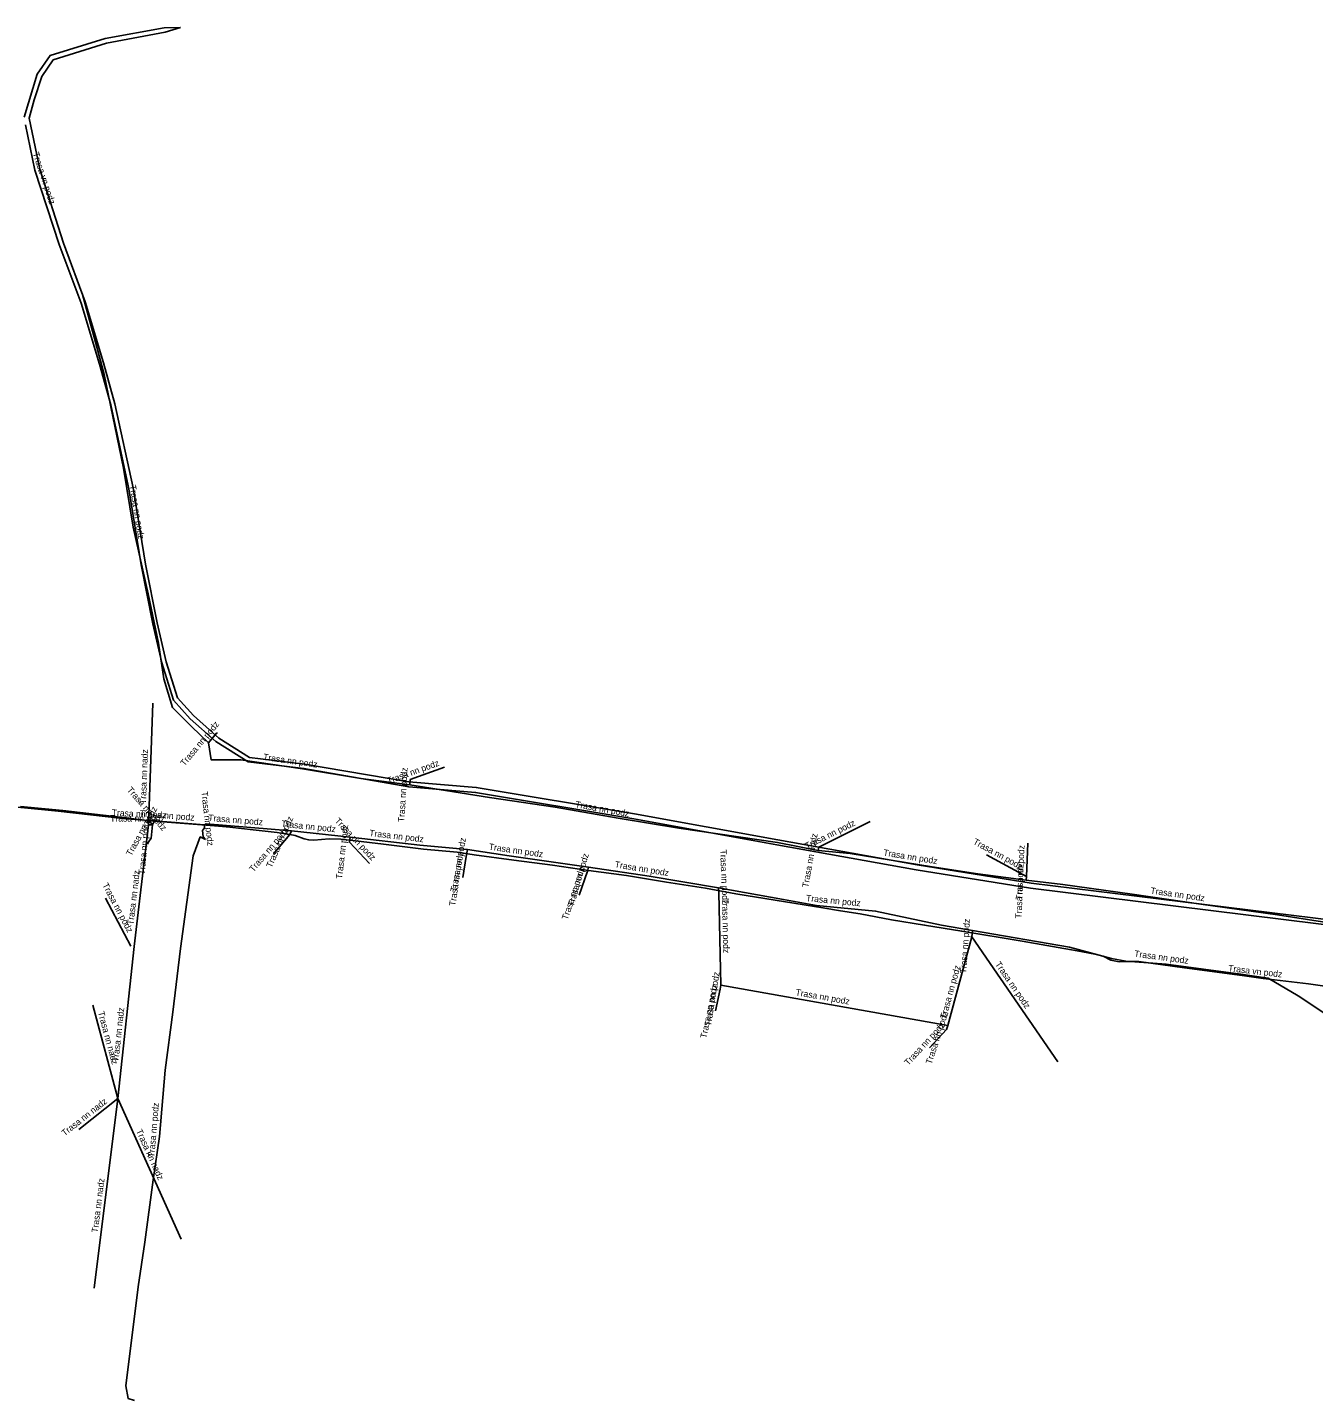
# Model space of a CAD drawing. Extents: x -704145 to -701313, y -1010090 to -1008177.
# Drawn here: x -702526.6 to -702325.8, y -1008863.1 to -1008648.8 of the extents above; entities that cross this region are included whole.
import ezdxf

# ---------------------------------------------------------------- set-up
doc = ezdxf.new("R2010")
doc.units = 0
for name, color, linetype in [('Level 11', 7, 'Continuous'), ('Level 20', 7, 'Continuous'), ('Level 21', 7, 'Continuous')]:
    doc.layers.add(name, color=color, linetype=linetype)

msp = doc.modelspace()

# ---------------------------------------------------------------- linework, layer by layer
at = {"layer": 'Level 11'}
for p, q in [((-702507.7, -1008773.21), (-702507.03, -1008754.23)), ((-702466.87, -1008766.17), (-702461.51, -1008764.24)), ((-702466.92, -1008767), (-702466.87, -1008766.17)), ((-702509.95, -1008792.21), (-702507.7, -1008773.21)), ((-702507.7, -1008773.21), (-702507.1, -1008773.21)), ((-702507.1, -1008773.21), (-702507.66, -1008772.57)), ((-702507.66, -1008772.57), (-702506.77, -1008772.61)), ((-702507.1, -1008773.21), (-702506.77, -1008772.61)), ((-702506.77, -1008772.61), (-702498.94, -1008773.22)), ((-702403.08, -1008776.71), (-702395.05, -1008772.73)), ((-702485.62, -1008774.72), (-702488.13, -1008777.68)), ((-702485.39, -1008774.19), (-702485.62, -1008774.72)), ((-702485.39, -1008774.19), (-702476.23, -1008775.13)), ((-702476.23, -1008775.13), (-702476.32, -1008775.93)), ((-702476.32, -1008775.93), (-702473.18, -1008779.25)), ((-702457.93, -1008777.1), (-702458.12, -1008778.18)), ((-702403.17, -1008777.23), (-702403.08, -1008776.71)), ((-702370.66, -1008781.3), (-702370.43, -1008776.08)), ((-702458.12, -1008778.18), (-702458.62, -1008781.44)), ((-702439.01, -1008779.84), (-702439.19, -1008780.46)), ((-702370.66, -1008781.3), (-702376.9, -1008777.9)), ((-702439.19, -1008780.46), (-702440.45, -1008784.23)), ((-702370.68, -1008781.88), (-702370.66, -1008781.3)), ((-702418.72, -1008783.05), (-702418.69, -1008783.77)), ((-702418.36, -1008798.26), (-702418.69, -1008783.77)), ((-702510.45, -1008792.15), (-702514.43, -1008784.66)), ((-702379.08, -1008789.71), (-702379.15, -1008790.71)), ((-702512.5, -1008815.97), (-702509.95, -1008792.21)), ((-702382.94, -1008804.53), (-702379.15, -1008790.71)), ((-702379.15, -1008790.71), (-702365.75, -1008810.2)), ((-702418.46, -1008798.9), (-702419.18, -1008802.25)), ((-702418.46, -1008798.89), (-702418.36, -1008798.26)), ((-702418.36, -1008798.26), (-702382.94, -1008804.53)), ((-702512.5, -1008815.97), (-702516.42, -1008801.39)), ((-702383.14, -1008805.17), (-702385.77, -1008808.02)), ((-702383.14, -1008805.17), (-702382.94, -1008804.53)), ((-702518.59, -1008820.78), (-702512.5, -1008815.97)), ((-702516.2, -1008845.55), (-702512.5, -1008815.97)), ((-702512.5, -1008815.97), (-702502.61, -1008837.9))]:
    msp.add_line(p, q, dxfattribs=at)
for points in [[(-702498.36, -1008760.45), (-702500.98, -1008757.87), (-702503.96, -1008754.9), (-702505.32, -1008750.45), (-702506.13, -1008744.89), (-702507.78, -1008737.15), (-702510.11, -1008726.77), (-702511.61, -1008717.57), (-702514.63, -1008702.91), (-702515.98, -1008697.86), (-702517.99, -1008690.46)], [(-702498.36, -1008760.45), (-702497.09, -1008758.92), (-702496.92, -1008758.89)], [(-702466.92, -1008767), (-702474.58, -1008766), (-702483.68, -1008764.49), (-702493.31, -1008763.1), (-702497.94, -1008763.07), (-702498.36, -1008760.45)], [(-702574.63, -1008766.64), (-702571.83, -1008766.98), (-702567.31, -1008767.31), (-702562.98, -1008767.5), (-702558.84, -1008768.14), (-702555.09, -1008768.64), (-702550.77, -1008768.98), (-702546.03, -1008769.22), (-702540.72, -1008769.59), (-702532.11, -1008770.1), (-702527.04, -1008770.58), (-702521.81, -1008771.09), (-702511.74, -1008772.25), (-702507.66, -1008772.57)], [(-702403.17, -1008777.23), (-702409.53, -1008776), (-702424.9, -1008773.73), (-702434.36, -1008772.2), (-702444.24, -1008770.45), (-702454.45, -1008768.95), (-702466.92, -1008767)], [(-702507.85, -1008776.25), (-702507.68, -1008775.84), (-702507.29, -1008775.3), (-702507.1, -1008773.21)], [(-702498.94, -1008773.22), (-702498.95, -1008773.7), (-702499.27, -1008774.13), (-702499.16, -1008775.09), (-702498.81, -1008775.5)], [(-702485.39, -1008774.19), (-702498.69, -1008773.08), (-702498.94, -1008773.22)], [(-702509.91, -1008863.1), (-702510.87, -1008862.8), (-702511.26, -1008860.79), (-702509.32, -1008845.37), (-702508.26, -1008838.38), (-702506.97, -1008828.63), (-702506.01, -1008821.86), (-702505.12, -1008811.51), (-702503.91, -1008802.49), (-702502.7, -1008792.55), (-702500.72, -1008778.07), (-702499.64, -1008775.12), (-702498.81, -1008775.5)], [(-702476.23, -1008775.13), (-702465.34, -1008776.41), (-702457.93, -1008777.1)], [(-702457.93, -1008777.1), (-702451.39, -1008778.07), (-702439.01, -1008779.84)], [(-702370.68, -1008781.88), (-702378.25, -1008780.9), (-702385.38, -1008779.76), (-702398.16, -1008777.7), (-702403.17, -1008777.23)], [(-702439.01, -1008779.84), (-702429.55, -1008781.26), (-702418.72, -1008783.05)], [(-702319.73, -1008789.11), (-702331.45, -1008787.28), (-702343.42, -1008785.6), (-702354.15, -1008784.06), (-702364.94, -1008782.53), (-702370.68, -1008781.88)], [(-702418.72, -1008783.05), (-702408.57, -1008784.89), (-702403.41, -1008785.8), (-702394.19, -1008786.68), (-702383.89, -1008788.91), (-702379.08, -1008789.71)], [(-702379.08, -1008789.71), (-702363.94, -1008792.3), (-702357.38, -1008794.12), (-702355.12, -1008794.5), (-702348.84, -1008794.98), (-702337.2, -1008796.54), (-702332.91, -1008797.14), (-702328.21, -1008799.91), (-702321.26, -1008804.56), (-702318.47, -1008806.08)]]:
    msp.add_lwpolyline(points, dxfattribs=at)
at = {"layer": 'Level 21'}
for points in [[(-702502.7, -1008648.75), (-702505.25, -1008648.79), (-702514.45, -1008650.49), (-702523.08, -1008653.11), (-702525.1, -1008656.06), (-702527.13, -1008662.73)], [(-702309.05, -1008789.82), (-702369.89, -1008782.31), (-702387.71, -1008779.45), (-702409.46, -1008775.55), (-702431.83, -1008771.52), (-702456.54, -1008767.39), (-702467.04, -1008766.5), (-702483.34, -1008763.74), (-702491.93, -1008762.71), (-702496.75, -1008759.68), (-702500.69, -1008756.17), (-702503.19, -1008753.41), (-702504.95, -1008747.76), (-702506.36, -1008741.71), (-702508.16, -1008732.51), (-702510.1, -1008720.64), (-702512.94, -1008707.51), (-702514.71, -1008701.13), (-702517.58, -1008691.56), (-702520.98, -1008682.4), (-702524.68, -1008670.85), (-702526.34, -1008662.93), (-702525.56, -1008660.05), (-702524.37, -1008656.42), (-702522.59, -1008653.82), (-702514.28, -1008651.18), (-702505.12, -1008649.48), (-702502.7, -1008648.75)], [(-702526.91, -1008663.97), (-702525.46, -1008671.05), (-702521.64, -1008682.63), (-702518.24, -1008691.78), (-702515.38, -1008701.32), (-702513.61, -1008707.68), (-702510.79, -1008720.77), (-702508.85, -1008732.64), (-702507.04, -1008741.86), (-702505.62, -1008747.94), (-702503.82, -1008753.76), (-702501.18, -1008756.67), (-702497.17, -1008760.24), (-702492.16, -1008763.39), (-702483.44, -1008764.43), (-702467.08, -1008767.3), (-702456.64, -1008768.18), (-702431.96, -1008772.31), (-702409.6, -1008776.34), (-702387.84, -1008780.24), (-702370.01, -1008783.1), (-702313.69, -1008790.08)], [(-702527.68, -1008770.39), (-702521.06, -1008770.97), (-702512.09, -1008772.04), (-702507.5, -1008772.62), (-702506.8, -1008772.65), (-702498.69, -1008773.28), (-702496.16, -1008773.5), (-702496.13, -1008773.5)], [(-702496.13, -1008773.5), (-702495.03, -1008773.6), (-702491.35, -1008774), (-702487.64, -1008774.44), (-702485.62, -1008774.72), (-702484.83, -1008774.9), (-702483.41, -1008775.42), (-702482.7, -1008775.59), (-702481.91, -1008775.62), (-702479.52, -1008775.41), (-702477.7, -1008775.49), (-702477.39, -1008775.52), (-702476.2, -1008775.62), (-702475.37, -1008775.72), (-702473.21, -1008775.98), (-702471.01, -1008776.26), (-702464.75, -1008777.02), (-702459.53, -1008777.49), (-702456.88, -1008777.89), (-702450.65, -1008778.73), (-702444.62, -1008779.5), (-702439.01, -1008780.36), (-702433.11, -1008781.16), (-702426.82, -1008782.18), (-702420.75, -1008783.12), (-702416.02, -1008783.98), (-702409.86, -1008784.99), (-702402.41, -1008786.16), (-702399.65, -1008786.65), (-702396.63, -1008787.12), (-702391.7, -1008788.07), (-702386.54, -1008788.88), (-702380.75, -1008789.85), (-702371.34, -1008791.41), (-702362.75, -1008792.91), (-702359.96, -1008793.4), (-702358.65, -1008793.75), (-702357.48, -1008794.34), (-702356.17, -1008794.62), (-702354.92, -1008794.54), (-702353.09, -1008794.55), (-702345.99, -1008795.55), (-702336.95, -1008796.76), (-702333.67, -1008797.23), (-702326.62, -1008798.05), (-702321.84, -1008798.75)]]:
    msp.add_lwpolyline(points, dxfattribs=at)

# ---------------------------------------------------------------- texts
at = {"layer": 'Level 20'}
for s, rotation, p in [('Trasa vn podz', 288.2462, (-702525.8, -1008668.4)), ('Trasa nn podz', 279.2602, (-702510.67, -1008720.25)), ('Trasa nn podz', 50.3051, (-702502.07, -1008764.14)), ('Trasa nn nadz', 87.9658, (-702508.09, -1008769.99)), ('Trasa nn podz', 351.7866, (-702489.86, -1008763.09)), ('Trasa nn podz', 19.8345, (-702470.27, -1008766.87)), ('Trasa nn podz', 86.5526, (-702467.77, -1008772.83)), ('Trasa nn podz', 311.1859, (-702511.14, -1008767.83)), ('Trasa nn podz', 276.5366, (-702499.46, -1008768.07)), ('Trasa nn podz', 357.4266, (-702513.47, -1008771.81)), ('Trasa nn podz', 61.1892, (-702510.4, -1008778.18)), ('Trasa nn podz', 355.5453, (-702509.08, -1008771.93)), ('Trasa nn podz', 349.9556, (-702441.14, -1008770.49)), ('Trasa nn podz', 84.8056, (-702508.31, -1008781.03)), ('Trasa nn podz', 355.2292, (-702498.41, -1008772.6)), ('Trasa nn podz', 66.541, (-702488.47, -1008780.02)), ('Trasa nn podz', 354.1408, (-702487.01, -1008773.52)), ('Trasa nn podz', 313.4044, (-702478.71, -1008772.68)), ('Trasa nn podz', 83.5812, (-702477.47, -1008781.72)), ('Trasa nn podz', 26.3363, (-702404.92, -1008777.06)), ('Trasa nn podz', 49.7186, (-702491.32, -1008780.68)), ('Trasa nn podz', 353.2963, (-702473.28, -1008774.97)), ('Trasa nn podz', 80.0223, (-702459.61, -1008783.74)), ('Trasa nn podz', 80.1807, (-702404.69, -1008783.08)), ('Trasa nn podz', 331.4449, (-702379.07, -1008776.16)), ('Trasa nn podz', 81.3568, (-702459.81, -1008785.95)), ('Trasa nn podz', 351.8634, (-702454.63, -1008777.1)), ('Trasa nn podz', 73.8108, (-702441.33, -1008786.05)), ('Trasa nn podz', 272.3859, (-702418.47, -1008777.11)), ('Trasa nn podz', 350.8433, (-702393.05, -1008778.02)), ('Trasa nn podz', 87.4333, (-702371.32, -1008784.95)), ('Trasa nn podz', 71.5423, (-702442.28, -1008788.15)), ('Trasa nn podz', 350.6149, (-702434.97, -1008779.86)), ('Trasa nn podz', 88.0251, (-702371.39, -1008787.86)), ('Trasa nn nadz', 83.2553, (-702510.06, -1008788.89)), ('Trasa nn podz', 298.0252, (-702514.95, -1008782.62)), ('Trasa nn podz', 354.5479, (-702405.08, -1008785.14)), ('Trasa nn podz', 351.8325, (-702351.34, -1008783.96)), ('Trasa nn podz', 271.3009, (-702418.17, -1008784.72)), ('Trasa nn podz', 85.9958, (-702380.05, -1008796.45)), ('Trasa nn podz', 352.3667, (-702353.86, -1008793.8)), ('Trasa nn podz', 304.5166, (-702375.6, -1008794.99)), ('Trasa nn podz', 80.8604, (-702419.9, -1008804.7)), ('Trasa nn podz', 74.6856, (-702383.19, -1008803.55)), ('Trasa vn podz', 353.3656, (-702339.19, -1008796.08)), ('Trasa nn podz', 78.0168, (-702420.61, -1008806.62)), ('Trasa nn podz', 349.957, (-702406.75, -1008799.81)), ('Trasa nn nadz', 285.0634, (-702515.61, -1008802.48)), ('Trasa nn nadz', 83.8769, (-702512.39, -1008810.29)), ('Trasa nn podz', 71.9979, (-702385.46, -1008810.68)), ('Trasa nn podz', 47.3816, (-702389.08, -1008810.88)), ('Trasa nn nadz', 38.2838, (-702520.79, -1008821.88)), ('Trasa nn podz', 85.0852, (-702506.8, -1008825.17)), ('Trasa nn nadz', 294.2825, (-702509.68, -1008821)), ('Trasa nn nadz', 82.8781, (-702515.62, -1008836.94))]:
    msp.add_text(s, height=1, rotation=rotation, dxfattribs=at).set_placement(p)
msp.add_text('Trasa nn podz', height=1, dxfattribs=at).set_placement((-702513.69, -1008772.71))

doc.saveas('drawing.dxf')
